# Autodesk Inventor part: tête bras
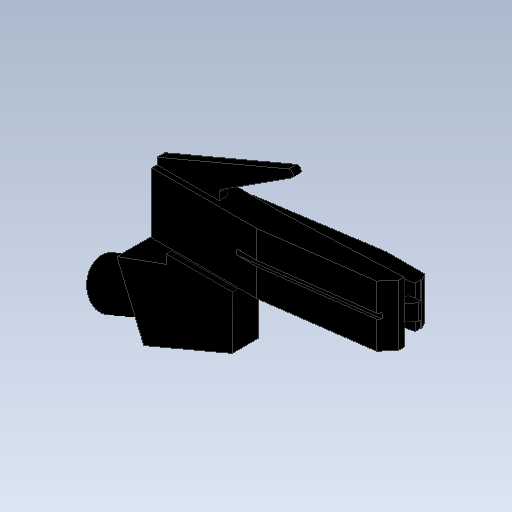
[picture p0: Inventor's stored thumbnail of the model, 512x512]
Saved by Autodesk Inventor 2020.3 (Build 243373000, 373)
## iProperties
Created: 2020-09
Part Number: tête bras
Material: Plastique ABS
Document SubType Name: Modeling
Designer: ficho
Density: 1.06 g/cm^3
Appearance: Anodisé - Noir
Mass: 3.06815 g
Surface Area: 44.2835 cm^2
Volume: 2.89448 cm^3
Author: ficho
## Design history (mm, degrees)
sketch "Esquisse1"
  geometry: L1 (0, 0)-(147.304, 0); L2 (147.304, 0)-(147.304, -67.514); L3 (147.304, -67.514)-(0, -67.514); L4 (0, -67.514)-(0, 0); L5 (65.53, -31.265)-(107.708, -31.265); L6 (107.708, -31.265)-(107.708, -42.864); L7 (107.708, -42.864)-(65.53, -42.864); L8 (65.53, -42.864)-(65.53, -31.265); L9 (68.281, -42.864)-(80.889, -42.864); L10 (80.889, -42.864)-(80.889, -45.844); L11 (80.889, -45.844)-(68.281, -45.844); L12 (68.281, -45.844)-(68.281, -42.864); L13 (68.281, -45.844)-(59.479, -49.053); L14 (59.479, -49.053)-(63.991, -61.429); L15 (63.991, -61.429)-(80.889, -54.28); L16 (80.889, -54.28)-(80.889, -45.844); L17 (65.53, -31.265)-(65.53, -30.01); L18 (65.53, -30.01)-(90.648, -19.382); L19 (91.168, -20.612)-(77.76, -29.27); L20 (77.418, -29.897)-(77.418, -31.265); L21 (60.085, -50.717)-(50.469, -54.785); L22 (50.469, -54.785)-(53.616, -63.417); L23 (53.616, -63.417)-(63.413, -59.845); A1 r 0.667 centre (90.908, -19.997) between (91.168, -20.612) and (90.648, -19.382); A2 r 0.747 centre (78.165, -29.897) between (77.76, -29.27) and (77.418, -29.897); 1 further point; 1 other entity
  constraints: 38 end point, 7 parallel, 5 perpendicular, 4 point on circle, 4 point on line, 3 tangent, 2 centre point, 2 horizontal, 2 vertical, 2 other
  dimensions: "d2" = 147.30375 distance between parallel lines of L2 L4
extrude "Extrusion1" new body sketch "Esquisse1" distance "d7" = 5; taper "d8" = 0 deg
sketch "Esquisse2"
  geometry: L1 (80.889, -54.28)-(80.889, -42.864) reference; L2 (68.281, -42.864)-(80.889, -42.864); L3 (80.889, -42.864)-(80.889, -44.114); L4 (80.889, -44.114)-(68.281, -44.114); L5 (68.281, -44.114)-(68.281, -42.864); 2 further points
  constraints: 8 end point, 2 parallel, 1 horizontal, 1 perpendicular, 1 point on line
  dimensions: "d9" = 1.25 distance of L2.end L3.end
extrude "Extrusion2" cut sketch "Esquisse2" distance "d10" = 1; taper "d11" = 0 deg
sketch "Esquisse3"
  geometry: L1 (77.418, -31.265)-(65.53, -31.265); L2 (65.53, -30.01)-(65.53, -31.265); L3 (90.648, -19.382)-(65.53, -30.01) reference; L4 (77.418, -31.265)-(77.418, -29.897) reference; L5 (77.76, -29.27)-(91.168, -20.612) reference; A1 r 0.747 centre (78.165, -29.897) between (77.76, -29.27) and (77.418, -29.897) reference; A2 r 0.667 centre (90.908, -19.997) between (91.168, -20.612) and (90.648, -19.382) reference; 1 further point
  constraints: 4 end point, 1 horizontal
extrude "Extrusion3" cut sketch "Esquisse3" distance "d13" = 1; taper "d14" = 0 deg
sketch "Esquisse4"
  geometry: L1 (-65.53, -30.01)-(-90.648, -19.382) reference; L2 (-65.53, -31.265)-(-65.53, -30.01) reference; L3 (-77.418, -31.265)-(-65.53, -31.265) reference; L4 (-77.418, -29.897)-(-77.418, -31.265) reference; L5 (-91.168, -20.612)-(-77.76, -29.27) reference; A1 r 0.667 centre (-90.908, -19.997) between (-90.648, -19.382) and (-91.168, -20.612) reference; A2 r 0.747 centre (-78.165, -29.897) between (-77.418, -29.897) and (-77.76, -29.27) reference; 1 further point
extrude "Extrusion4" cut sketch "Esquisse4" distance "d15" = 2.5; taper "d16" = 0 deg
sketch "Esquisse5"
  geometry: L1 (-15.358, 5)-(26.82, 5) reference; L2 (4.642, 5)-(26.82, 2); L3 (0, 0)-(26.82, 0) reference; L4 (26.82, 0)-(26.82, 5) reference; L5 (-15.358, 5)-(26.82, 5) reference; L6 (-15.358, 0)-(-15.358, 5) reference; L7 (-15.358, 0)-(-12.608, 0) reference; L8 (-12.608, 0)-(-12.608, 4) reference; L9 (-12.608, 4)-(0, 4) reference; L10 (0, 0)-(0, 4) reference; L11 (4.642, 5)-(26.82, 5); L12 (26.82, 5)-(26.82, 2); 2 further points
  constraints: 6 end point, 2 collinear, 2 point on line
  dimensions: "d17" = 20 distance of L2.start L1.start; "d18" = 2 distance of L3.end L2.end
extrude "Extrusion5" cut sketch "Esquisse5" extent not by distance; stored distance "d19" = 18.565; taper "d20" = 0 deg
sketch "Esquisse6"
  geometry: L1 (4.642, 0)-(26.82, -1); L2 (26.82, 0)-(-15.358, 0) reference; L3 (26.82, -1)-(26.82, 0); L4 (26.82, 0)-(4.642, 0); 1 further point
  constraints: 6 end point, 2 perpendicular
  dimensions: "d21" = 1 distance from line of L1.end L2
extrude "Extrusion6" join sketch "Esquisse6" stored distance "d22" = 10; taper "d23" = 0 deg
chamfer "Chanfrein1" distance "d24" = 2; stored, may be unused: second distance "d25" = 2, angle "d26" = 45 deg
sketch "Esquisse7"
  geometry: L1 (0, 0)-(0, 11.599) reference; L2 (20.38, 11.599)-(20.38, 0) reference; L3 (0, 5.3)-(20.38, 5.3); L4 (20.38, 5.3)-(20.38, 6.3); L5 (20.38, 6.3)-(0, 6.3); L6 (0, 6.3)-(0, 5.3); L7 (20.38, 0)-(0, 0) reference; L8 (0, 11.599)-(20.38, 11.599) reference; L9 (0, 5.3)-(-24.9, 5.3); L10 (-24.9, 5.3)-(-24.9, 6.3); L11 (-24.9, 6.3)-(0, 6.3); L12 (0, 6.3)-(0, 5.3); L13 (20.38, 5.3)-(23.852, 5.3); L14 (23.852, 5.3)-(23.852, 6.3); L15 (23.852, 6.3)-(20.38, 6.3); L16 (20.38, 6.3)-(20.38, 5.3); 6 further points
  constraints: 24 end point, 6 parallel, 3 horizontal, 3 perpendicular, 3 point on line
  dimensions: "d27" = 5.3 distance between parallel lines of L3 L7; "d28" = 1 distance between parallel lines of L3 L5; "d29" = 5.29897 distance between parallel lines of L8 L5 (derived)
extrude "Extrusion7" cut sketch "Esquisse7" distance "d30" = 0.5; taper "d31" = 0 deg
sketch "Esquisse8"
  geometry: L1 (-18.348, 0)-(-18.348, 5) reference; L2 (-18.348, 0)-(-12.273, 0); L3 (-14.348, -4)-(-18.348, -4); L4 (-18.348, -4)-(-18.348, 0); L5 (-14.348, -4)-(-12.348, 0); L6 (-18.348, 0)-(0, 0) reference; L7 (-12.348, 0)-(-12.273, 0); L8 (-8.324, 0)-(-17.681, 0) reference; 2 further points
  constraints: 10 end point, 1 collinear, 1 horizontal, 1 parallel, 1 point on line
  dimensions: "d33" = 6 distance from line of L5.end L1; "d34" = 4 distance between parallel lines of L3 L2; "d35" = 4 distance from line of L3.start L4
extrude "Extrusion8" join sketch "Esquisse8" stored distance "d36" = 10; taper "d37" = 0 deg
sketch "Esquisse9"
  geometry: L1 (0.667, 13.156)-(0, 0) reference; L2 (0.667, 13.156)-(0, 13.19) reference; L3 (0, 0)-(0, 13.19) reference; 1 further point
extrude "Extrusion9" join sketch "Esquisse9" stored distance "d38" = 10; taper "d39" = 0 deg
sketch "Esquisse10"
  geometry: L1 (0, 0)-(0, 13.19) reference; C1 r 4.25 at (4.5, 6.595); 1 further point
  constraints: 1 centre point
  dimensions: "d40" = 8.5 diameter of C1; "d41" = 4.5 distance from line of C1.centre L1
extrude "Extrusion10" join sketch "Esquisse10" distance "d42" = 9; taper "d43" = 0 deg
sketch "Esquisse11"
  geometry: L1 (-1.5, -6.533)-(-1.5, 4.149) reference; C1 r 4.25 at (0, 0) reference; 1 further point
hole "Perçage1" sketch "Esquisse11" at (0, 0) diameter "d44" = 6; stored, may be unused: countersink angle "d48" = 90 deg, drill point angle "d50" = 118 deg; dims "d45" = 6, "d46" = 4, "d47" = 2, "d49" = 8
feature "Coque1" dims "d51" = 1
sketch "Esquisse12"
  geometry: L1 (3, 12.138)-(3, 1) reference; L2 (3, 11.289)-(0.351, 11.289); L3 (0.351, 11.289)-(0.351, 2.111); L4 (0.351, 2.111)-(3, 2.111); L5 (3, 2.111)-(3, 11.289); 2 further points
  constraints: 8 end point, 2 parallel, 1 horizontal, 1 perpendicular, 1 point on line
extrude "Extrusion11" cut sketch "Esquisse12" stored distance "d52" = 10; taper "d53" = 0 deg
node "Plan de construction1"
sketch "Esquisse13"
  geometry: L1 (42.178, 5)-(42.178, 4) reference; L2 (42.178, 5)-(43.545, 6.453); L3 (43.545, 6.453)-(43.545, 6.898); L4 (43.545, 6.898)-(41.258, 6.898); L5 (41.178, 4.955)-(41.178, 4.375) reference; L6 (41.258, 6.898)-(41.178, 4.955); L7 (20, 4)-(42.178, 5) reference; L8 (41.178, 4.955)-(42.178, 5); 1 further point
  constraints: 10 end point, 1 collinear, 1 parallel, 1 perpendicular
extrude "Extrusion12" join sketch "Esquisse13" stored distance "d55" = 3; taper "d56" = 0 deg
sketch "Esquisse14"
  geometry: L1 (13.739, 0.004)-(42.402, 6.898); L2 (41.258, 6.898)-(43.545, 6.898) reference; L3 (42.402, 7.949)-(42.402, 6.898); L4 (42.402, 7.949)-(42.608, 7.949); L5 (42.608, 7.949)-(41.821, 9.312); L6 (41.821, 9.312)-(34.497, 9.312); L7 (34.497, 9.312)-(12.317, 5.916); L8 (12.317, 5.916)-(13.739, 0.004); 1 further point
  constraints: 14 end point, 2 perpendicular, 1 horizontal, 1 midpoint
extrude "Extrusion13" join sketch "Esquisse14" stored distance "d57" = 8; taper "d58" = 0 deg
node "Solide1"
node "Image1"
node "Boucle projetée1"
node "Boucle projetée2"
node "Boucle projetée3"
other parameters: "d54" = -5.8
